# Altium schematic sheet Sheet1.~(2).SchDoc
size A4
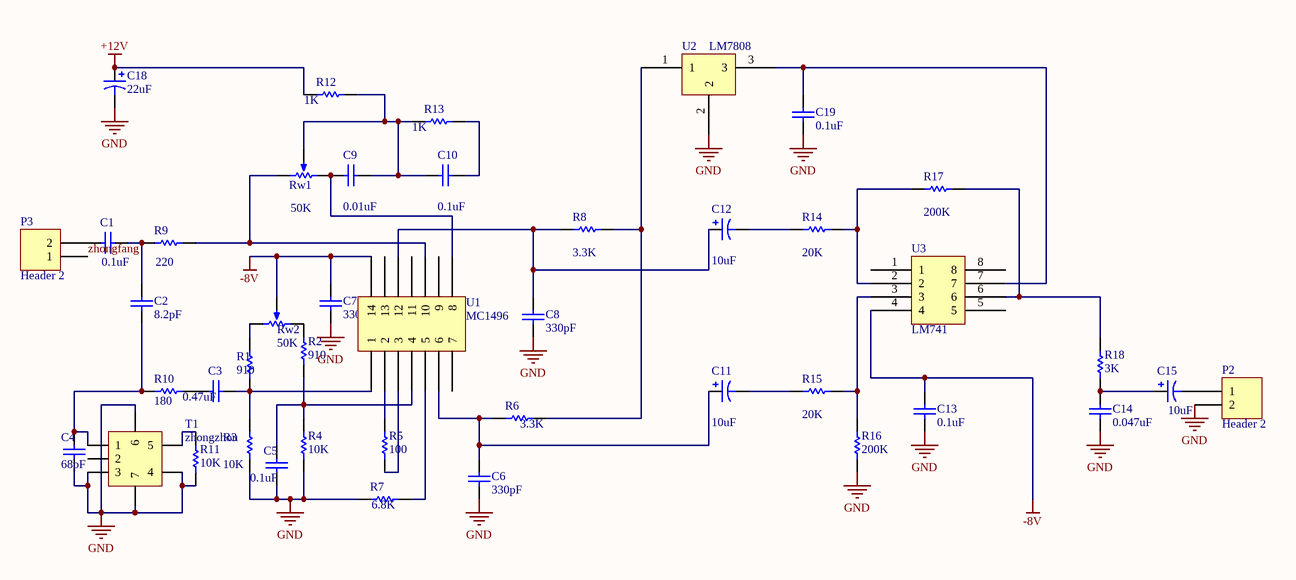
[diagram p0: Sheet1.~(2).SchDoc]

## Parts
C1  value 0.1uF  [2012[0805]]  (hidden comment: Cap)
C2  value 8.2pF  [2012[0805]]  (hidden comment: Cap)
C3  value 0.47uF  [2012[0805]]  (hidden comment: Cap)
C4  value 68pF  [2012[0805]]  (hidden comment: Cap)
C5  value 0.1uF  [2012[0805]]  (hidden comment: Cap)
C6  value 330pF  [2012[0805]]  (hidden comment: Cap)
C7  value 330pF  [2012[0805]]  (hidden comment: Cap)
C8  value 330pF  [2012[0805]]  (hidden comment: Cap)
C9  value 0.01uF  [2012[0805]]  (hidden comment: Cap)
C10  value 0.1uF  [2012[0805]]  (hidden comment: Cap)
C11  value 10uF  [C1206]  (hidden comment: Cap Pol1)
C12  value 10uF  [C1206]  (hidden comment: Cap Pol1)
C13  value 0.1uF  [2012[0805]]  (hidden comment: Cap)
C14  value 0.047uF  [2012[0805]]  (hidden comment: Cap)
C15  value 10uF  [C1206]  (hidden comment: Cap Pol1)
C18  value 22uF  [C1206]  (hidden comment: Cap Pol1)
C19  value 0.1uF  [2012[0805]]  (hidden comment: Cap)
P2  Header 2  [HDR1X2]
P3  Header 2  [HDR1X2]
R1  value 910  [2012[0805]]  (hidden comment: Res1)
R2  value 910  [2012[0805]]  (hidden comment: Res1)
R3  value 10K  [2012[0805]]  (hidden comment: Res1)
R4  value 10K  [2012[0805]]  (hidden comment: Res1)
R5  value 100  [2012[0805]]  (hidden comment: Res1)
R6  value 3.3K  [2012[0805]]  (hidden comment: Res1)
R7  value 6.8K  [2012[0805]]  (hidden comment: Res1)
R8  value 3.3K  [2012[0805]]  (hidden comment: Res1)
R9  value 220  [2012[0805]]  (hidden comment: Res1)
R10  value 180  [2012[0805]]  (hidden comment: Res1)
R11  value 10K  [2012[0805]]  (hidden comment: Res1)
R12  value 1K  [2012[0805]]  (hidden comment: Res1)
R13  value 1K  [2012[0805]]  (hidden comment: Res1)
R14  value 20K  [2012[0805]]  (hidden comment: Res1)
R15  value 20K  [2012[0805]]  (hidden comment: Res1)
R16  value 200K  [2012[0805]]  (hidden comment: Res1)
R17  value 200K  [2012[0805]]  (hidden comment: Res1)
R18  value 3K  [2012[0805]]  (hidden comment: Res1)
Rw1  value 50K  [VR5]  (hidden comment: RPot)
Rw2  value 50K  [VR5]  (hidden comment: RPot)
T1  zhongzhou
U1  MC1496  [MC1496]
U2  LM7808  [LM7808]
U3  LM741  [LM741]

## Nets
+12V: C18.1 R12.1
-8V: C7.2 C13.2 Rw2.3(TAP) U1.14 U3.4
GND: C4.1 C5.1 C6.1 C7.1 C8.1 C13.1 C14.1 C18.2 C19.1 P2.2 R3.1 R4.1 R7.1 R11.1 R16.1 T1.3 T1.4 T1.6 T1.7 U2.2
zhongfang: P3.1
NetC1_1: C1.1 P3.2
NetC1_2: C1.2 C2.2 R9.1
NetC2_1: C2.1 C4.2 R10.1 T1.1
NetC3_1: C3.1 R10.2
NetC3_2: C3.2 R1.1 R3.2 U1.1
NetC5_2: C5.2 R2.1 R4.2 U1.4
NetC6_2: C6.2 C11.1 R6.1 U1.6
NetC8_2: C8.2 C12.1 R8.1 U1.12
NetC9_1: C9.1 Rw1.1(TOP) U1.8
NetC9_2: C9.2 C10.1 R12.2 R13.1 Rw1.3(TAP)
NetC10_2: C10.2 R13.2
NetC11_2: C11.2 R15.1
NetC12_2: C12.2 R14.1
NetC14_2: C14.2 C15.1 R18.1
NetC15_2: C15.2 P2.1
NetC19_2: C19.2 U2.3 U3.7
NetR1_2: R1.2 Rw2.2(BOT)
NetR2_2: R2.2 Rw2.1(TOP)
NetR5_1: R5.1 U1.3
NetR5_2: R5.2 U1.2
NetR6_2: R6.2 R8.2 U2.1
NetR7_2: R7.2 U1.5
NetR9_2: R9.2 Rw1.2(BOT) U1.10
NetR11_2: R11.2 T1.5
NetR14_2: R14.2 R17.1 U3.2
NetR15_2: R15.2 R16.2 U3.3
NetR17_2: R17.2 R18.2 U3.6

Not connected (* = marked no-connect by the designer): T1 2; U1 7 9 11 13; U3 1 5 8

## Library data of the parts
C1-C10 C13 C14 C19 = Cap: Capacitor
C11 C12 C15 C18 = Cap Pol1: Polarized Capacitor (Radial)
P2 P3 = Header 2: Header, 2-Pin
R1-R18 = Res1: Resistor
Rw1 Rw2 = RPot: Potentiometer; Sim Note: Enter the Resistance value and the set point into parameter fields.; Set Position: 0.5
